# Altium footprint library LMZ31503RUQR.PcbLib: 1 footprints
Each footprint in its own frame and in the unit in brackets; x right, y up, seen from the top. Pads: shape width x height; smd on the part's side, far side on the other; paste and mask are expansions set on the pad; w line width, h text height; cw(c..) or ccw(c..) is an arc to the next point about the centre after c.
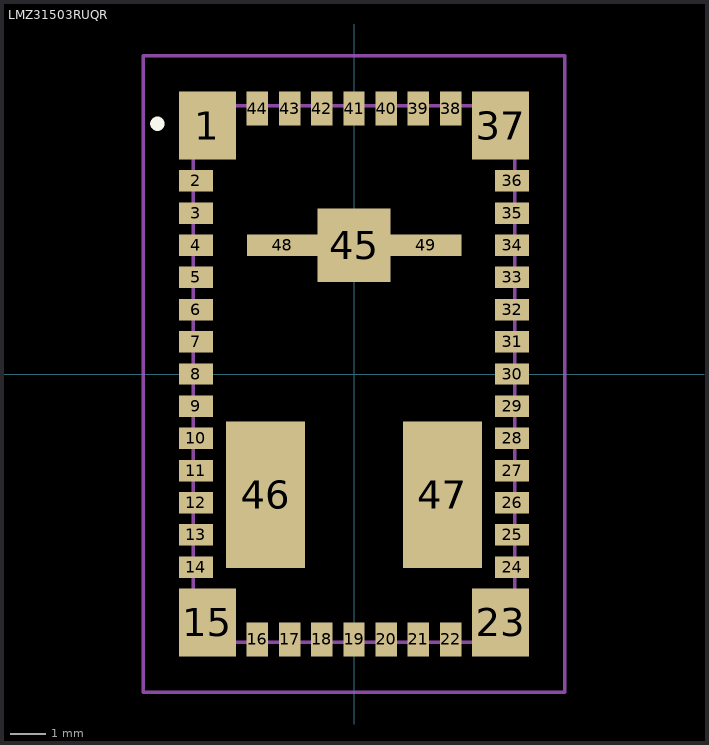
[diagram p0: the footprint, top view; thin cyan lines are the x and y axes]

## LMZ31503RUQR [mm]
pads (49):
  rect 1.6x1.9 smd: 1(-4.1,6.95) 15(-4.1,-6.95) 23(4.1,-6.95) 37(4.1,6.95)
  rect 0.95x0.6 smd: 2(-4.425,5.4) 3(-4.425,4.5) 4(-4.425,3.6) 5(-4.425,2.7) 6(-4.425,1.8) 7(-4.425,0.9) 8(-4.425,0) 9(-4.425,-0.9) 10(-4.425,-1.8) 11(-4.425,-2.7) 12(-4.425,-3.6) 13(-4.425,-4.5) 14(-4.425,-5.4) 24(4.425,-5.4) 25(4.425,-4.5) 26(4.425,-3.6) 27(4.425,-2.7) 28(4.425,-1.8) 29(4.425,-0.9) 30(4.425,0) 31(4.425,0.9) 32(4.425,1.8) 33(4.425,2.7) 34(4.425,3.6) 35(4.425,4.5) 36(4.425,5.4)
  rect 0.6x0.95 smd: 16(-2.7,-7.425) 17(-1.8,-7.425) 18(-0.9,-7.425) 19(0,-7.425) 20(0.9,-7.425) 21(1.8,-7.425) 22(2.7,-7.425) 38(2.7,7.425) 39(1.8,7.425) 40(0.9,7.425) 41(0,7.425) 42(-0.9,7.425) 43(-1.8,7.425) 44(-2.7,7.425)
  rect 2.05x2.05 smd: 45(0,3.6)
  rect 2.2x4.1 smd: 46(-2.475,-3.375) 47(2.475,-3.375)
  rect 1.975x0.6 smd: 48(-2.012,3.6) 49(2.013,3.6)
Top Overlay:
  lines w0.2: -5.6,7 cw(c-5.5,7) -5.4,7 ; -5.6,7 -5.6,7 ; -5.6,7 ccw(c-5.5,7) -5.4,7 ; -5.4,7 -5.4,7
Mechanical 15:
  lines w0.1: -4.5,-7.5 4.5,-7.5 4.5,7.5 -4.5,7.5 -4.5,-7.5
Mechanical 20:
  lines w0.1: -5.9,-8.9 5.9,-8.9 5.9,8.9 -5.9,8.9 -5.9,-8.9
